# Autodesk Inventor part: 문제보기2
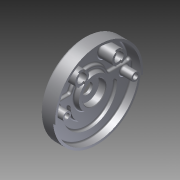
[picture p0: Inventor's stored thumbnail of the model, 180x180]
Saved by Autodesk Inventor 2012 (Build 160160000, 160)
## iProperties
Created: 2015-04
Part Number: 문제보기2
Material: Default
Document SubType Name: Modeling
Designer: Owner
Density: 1 g/cm^3
Author: Owner
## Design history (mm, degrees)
sketch "스케치2"
  geometry: C1 r 95 at (0, 0); 1 further point
  constraints: 1 centre point, 1 coincident
  dimensions: "d3" = 190 diameter of C1
extrude "돌출1" new body sketch "스케치2" distance "d4" = 32; taper "d5" = 0 deg
sketch "스케치3"
  geometry: C1 r 95 at (0, 0) reference; C2 r 90 at (0, 0)
  constraints: 1 centre point, 1 coincident
  dimensions: "d6" = 180 diameter of C2
extrude "돌출2" cut sketch "스케치3" distance "d7" = 20.5; taper "d8" = 0 deg
sketch "스케치4"
  geometry: L1 (-79.667, -14)-(79.667, -14); C1 r 90 at (0, 0) reference; C2 r 90 at (0, 0) reference; C3 r 90 at (0, 0) reference; C4 r 95 at (0, 0) reference; A1 r 41 centre (0, -14) between (-41, -14) and (41, -14); A2 r 59 centre (0, -14) between (-59, -14) and (59, -14); A3 r 9 centre (-50, -14) between (-41, -14) and (-59, -14); A4 r 9 centre (50, -14) between (59, -14) and (41, -14); 1 further point
  constraints: 8 point on circle, 4 centre point, 2 coincident, 2 end point, 2 point on line, 2 tangent, 1 horizontal, 1 midpoint, 1 vertical alignment
  dimensions: "d9" = 14 distance from line of C1.centre L1; "d10" = 82 diameter of A1; "d11" = 118 diameter of A2; "d12" = 18 diameter of A3; "d13" = 18 diameter of A4
extrude "돌출3" cut sketch "스케치4" distance "d14" = 7; taper "d15" = 0 deg
sketch "스케치5"
  geometry: L1 (-83.283, 12)-(83.283, 12); C1 r 90 at (0, 0) reference; A1 r 42 centre (0, 0) between (40.249, 12) and (-40.249, 12); A2 r 5 centre (-83.283, 17) between (-88.182, 18) and (-83.283, 12); A3 r 5 centre (83.283, 17) between (83.283, 12) and (88.182, 18); A4 r 90 centre (0, 0) between (-88.182, 18) and (88.182, 18) reference; A5 r 5 centre (-43.818, 17) between (-43.818, 12) and (-39.156, 15.191); A6 r 5 centre (43.818, 17) between (39.156, 15.191) and (43.818, 12); A7 r 90 centre (0, 0) between (88.182, 18) and (-88.182, 18)
  constraints: 16 point on circle, 8 tangent, 6 centre point, 4 point on line, 2 coincident, 2 end point, 1 horizontal
  dimensions: "d16" = 84 diameter of A1; "d17" = 12 distance from line of L1 A1.centre; "d18" = 10 diameter of A2; "d19" = 10 diameter of A3; "d20" = 10 diameter of A5; "d21" = 10 diameter of A6
extrude "돌출4" cut sketch "스케치5" distance "d22" = 7; taper "d23" = 0 deg
sketch "스케치6"
  geometry: L1 (-83.283, 12)-(-43.818, 12) reference; L2 (-56.202, 52)-(58.852, 52); L3 (0, 0)-(0, 134.318); C1 r 15 at (-40, 52); A1 r 42 centre (0, 0) between (39.156, 15.191) and (-39.156, 15.191) reference; A2 r 90 centre (0, 0) between (88.182, 18) and (-88.182, 18) reference
  constraints: 4 end point, 1 centre point, 1 parallel, 1 perpendicular, 1 point on line
  dimensions: "d24" = 52 distance from line of L2 A1.centre; "d25" = 30 diameter of C1; "d26" = 40 distance from line of L3 C1.centre
extrude "돌출5" join sketch "스케치6" distance "d27" = 30.5; taper "d28" = 0 deg
sketch "스케치7"
  geometry: C1 r 15 at (0, 0) reference; C2 r 10 at (0, 0); 1 further point
  constraints: 1 centre point, 1 coincident
  dimensions: "d29" = 20 diameter of C2
extrude "돌출6" cut sketch "스케치7" stored distance "d30" = 30.5; taper "d31" = 0 deg
sketch "스케치8"
  geometry: L1 (6, 13.748)-(6, 8); L2 (6, -8)-(6, -13.748); L3 (0, 15)-(0, 10); L4 (0, -10)-(0, -15); L5 (-6, 13.748)-(-6, 8); L6 (-6, -8)-(-6, -13.748); C1 r 10 at (0, 0) reference; C2 r 15 at (0, 0) reference; A1 r 10 centre (0, 0) between (6, 8) and (6, -8); A2 r 15 centre (0, 0) between (-6, 13.748) and (0, 15); 4 further points
  constraints: 12 end point, 12 point on circle, 8 parallel, 3 coincident, 2 centre point, 2 concentric, 2 midpoint, 2 vertical, 2 vertical alignment
  dimensions: "d34" = 6 distance between parallel lines of L5 L3; "d35" = 6 distance between parallel lines of L3 L1; "d36" = 6 distance between parallel lines of L4 L2; "d37" = 6 distance between parallel lines of L6 L4
extrude "돌출7" cut sketch "스케치8" distance "d38" = 3; taper "d39" = 0 deg
sketch "스케치9"
  geometry: C1 r 35 at (0, 0); A1 r 90 centre (0, 0) between (-88.182, 18) and (88.182, 18) reference
  constraints: 1 centre point, 1 coincident
  dimensions: "d40" = 70 diameter of C1
extrude "돌출8" join sketch "스케치9" distance "d41" = 10; taper "d42" = -10 deg
hole "구멍1" diameter "d45" = 23; stored, may be unused: countersink angle "d49" = 90 deg, drill point angle "d51" = 118 deg; dims "d43" = 10, "d44" = 10, "d46" = 6, "d47" = 50, "d48" = 15, "d50" = 8
sketch "스케치10"
  geometry: L1 (-43.818, 12)-(-83.283, 12) reference; L2 (-83.283, 0)-(79.95, 0); C1 r 9 at (-74, 0); C2 r 9 at (74, 0); A1 r 90 centre (0, 0) between (-88.182, 18) and (88.182, 18) reference; A2 r 15 centre (-40, 52) between (-46, 65.748) and (-46, 38.252) reference; A3 r 74 centre (0, 0) between (-74, 0) and (74, 0)
  constraints: 3 centre point, 2 end point, 2 point on circle, 2 point on line, 1 coincident, 1 parallel
  dimensions: "d52" = 52 distance from line of A2.centre L2; "d53" = 148 diameter of A3; "d54" = 18 diameter of C1; "d55" = 18 diameter of C2
extrude "돌출9" join sketch "스케치10" distance "d56" = 25; taper "d57" = 0 deg
hole "구멍2" diameter "d60" = 11; stored, may be unused: countersink angle "d64" = 90 deg, drill point angle "d66" = 0 deg; dims "d58" = 10, "d59" = 10, "d61" = 6, "d62" = 18, "d63" = 15, "d65" = 11
sketch "스케치11"
  geometry: C1 r 5.5 at (74, 0) reference; C2 r 9 at (74, 0)
  constraints: 1 centre point, 1 coincident
  dimensions: "d67" = 18 diameter of C2
extrude "돌출10" cut sketch "스케치11" distance "d68" = 11; taper "d69" = 0 deg
sketch "스케치12"
  geometry: C1 r 9 at (0, 0) reference; C2 r 5.5 at (0, 0); 1 further point
  constraints: 1 centre point, 1 coincident
  dimensions: "d70" = 11 diameter of C2
extrude "돌출11" cut sketch "스케치12" stored distance "d71" = 11; taper "d72" = 0 deg
sketch "스케치13"
  geometry: C1 r 5.5 at (-74, 0) reference; C2 r 9 at (-74, 0)
  constraints: 1 centre point, 1 coincident
  dimensions: "d73" = 18 diameter of C2
extrude "돌출12" cut sketch "스케치13" distance "d74" = 11; taper "d75" = 0 deg
sketch "스케치14"
  geometry: L1 (0, 0)-(0, -72); L2 (0, 0)-(-8.132, -8.132); L3 (-36.062, -36.062)-(-50.912, -50.912); L4 (0, 0)-(8.132, -8.132); L5 (36.062, -36.062)-(50.912, -50.912); C1 r 95 at (0, 0) reference; A1 r 11.5 centre (0, 0) between (-8.132, -8.132) and (8.132, -8.132) reference; A2 r 72 centre (0, 0) between (0, -72) and (-50.912, -50.912); A3 r 51 centre (0, 0) between (-36.062, -36.062) and (36.062, -36.062)
  constraints: 10 end point, 7 point on circle, 2 centre point, 2 coincident, 1 vertical
  dimensions: "d76" = 144 diameter of A2; "d77" = 102 diameter of A3; "d80" = 45 deg angle of L1 L5; "d81" = 45 deg angle of L1 L3
extrude "돌출13" join sketch "스케치14" distance "d82" = 5; taper "d83" = 0 deg
sketch "스케치15"
  geometry: C1 r 88 at (0, 0); A1 r 72 centre (0, 0) between (-50.912, -50.912) and (50.912, -50.912) reference; A2 r 51 centre (0, 0) between (-36.062, -36.062) and (36.062, -36.062) reference
  constraints: 1 centre point, 1 coincident, 1 other
  dimensions: "d84" = 176 diameter of C1
extrude "돌출14" join sketch "스케치15" distance "d85" = 0.5; taper "d86" = 0 deg
fillet "모깎기1" dims "d87" = 5
fillet "모깎기2" dims "d88" = 4
chamfer "모따기1" distance "d89" = 1; stored, may be unused: second distance "d90" = 2, angle "d91" = 45 deg
chamfer "모따기2" distance "d92" = 1; stored, may be unused: second distance "d93" = 2, angle "d94" = 45 deg
fillet "모깎기3" dims "d95" = 5
sketch "스케치16"
  geometry: L1 (-95, 0)-(95, 0); L2 (0, 0)-(-94.638, -8.28); L3 (0, 0)-(94.638, -8.28); C1 r 90 at (0, 0) reference; A1 r 95 centre (0, 0) between (-94.638, -8.28) and (94.638, -8.28) reference; A2 r 95 centre (0, 0) between (95, 0) and (-95, 0); A3 r 95 centre (0, 0) between (-94.638, -8.28) and (94.638, -8.28); A4 r 90 centre (0, 0) between (90, 0) and (-90, 0); A5 r 90 centre (0, 0) between (-89.658, -7.844) and (89.658, -7.844)
  constraints: 10 point on circle, 6 end point, 4 centre point, 4 point on line, 3 coincident, 1 horizontal
  dimensions: "d96" = 5 deg angle of L1 L2; "d97" = 5 deg angle of L1 L3
extrude "돌출15" cut sketch "스케치16" distance "d98" = 5; taper "d99" = 0 deg
fillet "모깎기4" dims "d100" = 3
fillet "모깎기5" dims "d101" = 0.3
fillet "모깎기6" dims "d102" = 3
fillet "모깎기7" dims "d103" = 3
fillet "모깎기8" dims "d104" = 3
fillet "모깎기9" dims "d105" = 3
fillet "모깎기10" dims "d106" = 3
fillet "모깎기11" dims "d107" = 1
node "솔리드2"
mirror "대칭1"
node "투영된 루프1"
other parameters: "d32" = 6, "d33" = 6, "d78" = 45 deg, "d79" = 45 deg
